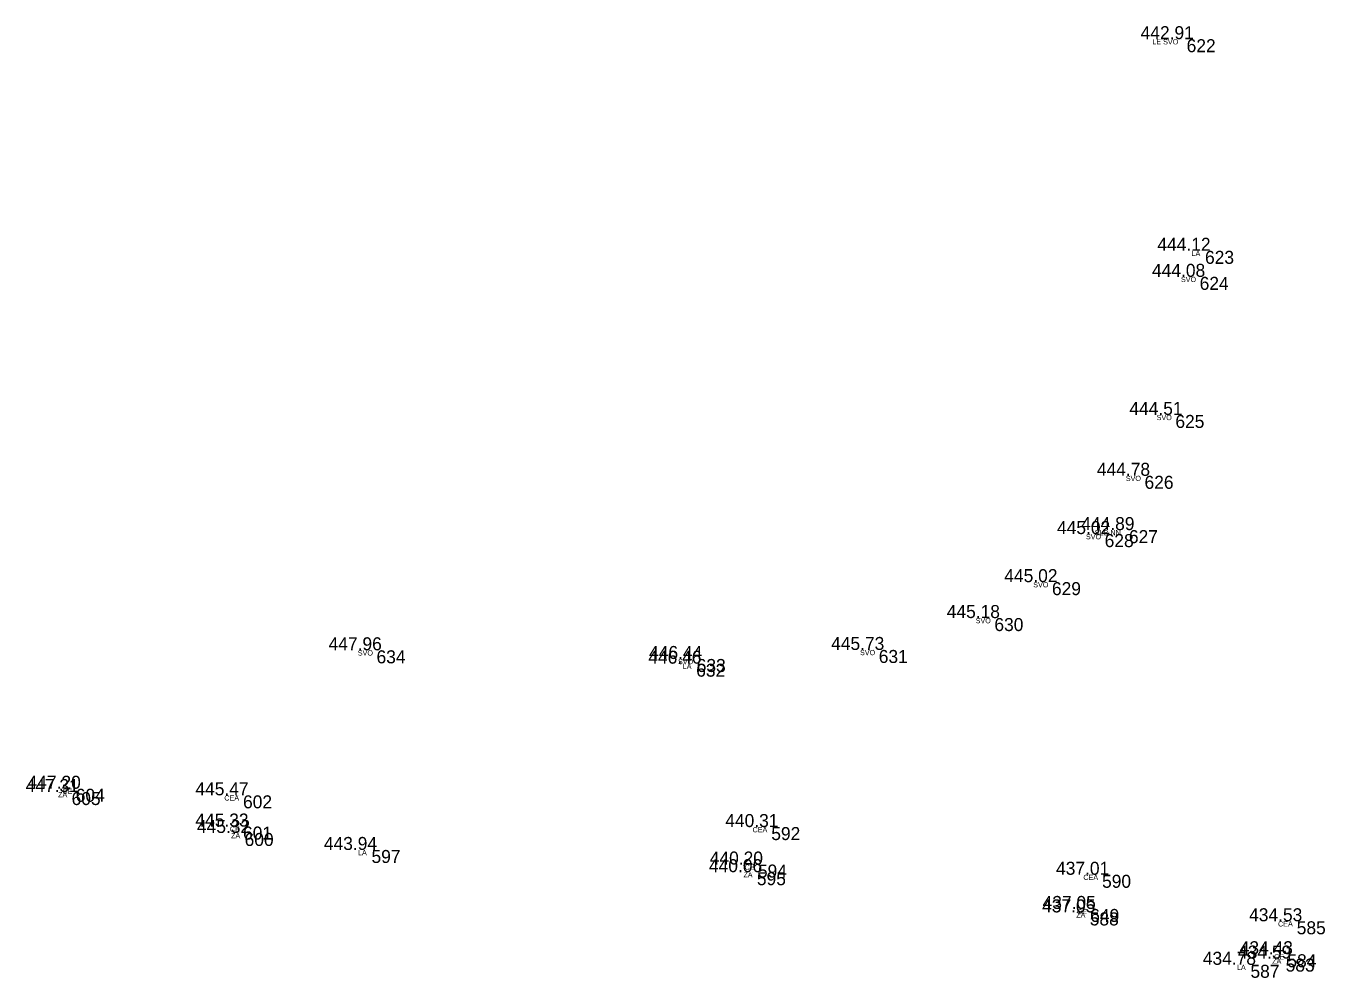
# Model space of a CAD drawing. Extents: x -639373 to -639057, y -1138651 to -1138359.
# Drawn here: x -639373.4 to -639298.5, y -1138578.8 to -1138523.9 of the extents above; entities that cross this region are included whole.
import ezdxf

# ---------------------------------------------------------------- set-up
doc = ezdxf.new("R2010")
doc.units = 0
for name, color, linetype in [('Vrstva 11', 7, 'Continuous'), ('Vrstva 12', 7, 'Continuous'), ('Vrstva 13', 7, 'Continuous'), ('Vrstva 57', 7, 'Continuous')]:
    doc.layers.add(name, color=color, linetype=linetype)

msp = doc.modelspace()

# ---------------------------------------------------------------- linework, layer by layer
at = {"layer": 'Vrstva 11'}
for p, q in [((-639306.73, -1138524.65), (-639306.73, -1138524.65)), ((-639305.67, -1138536.85), (-639305.67, -1138536.85)), ((-639305.98, -1138538.35), (-639305.98, -1138538.35)), ((-639307.38, -1138546.31), (-639307.38, -1138546.31)), ((-639309.16, -1138549.82), (-639309.16, -1138549.82)), ((-639310.06, -1138552.95), (-639310.06, -1138552.95)), ((-639311.46, -1138553.18), (-639311.46, -1138553.18)), ((-639314.5, -1138555.95), (-639314.5, -1138555.95)), ((-639317.82, -1138558.02), (-639317.82, -1138558.02)), ((-639353.46, -1138559.88), (-639353.46, -1138559.88)), ((-639334.99, -1138560.38), (-639334.99, -1138560.38)), ((-639324.49, -1138559.86), (-639324.49, -1138559.86)), ((-639335.02, -1138560.65), (-639335.02, -1138560.65)), ((-639370.81, -1138567.86), (-639370.81, -1138567.86)), ((-639371.05, -1138568.05), (-639371.05, -1138568.05)), ((-639361.16, -1138568.24), (-639361.16, -1138568.24)), ((-639361.16, -1138570.04), (-639361.16, -1138570.04)), ((-639330.69, -1138570.07), (-639330.69, -1138570.07)), ((-639361.07, -1138570.41), (-639361.07, -1138570.41)), ((-639353.75, -1138571.39), (-639353.75, -1138571.39)), ((-639331.46, -1138572.23), (-639331.46, -1138572.23)), ((-639331.52, -1138572.67), (-639331.52, -1138572.67)), ((-639311.61, -1138572.82), (-639311.61, -1138572.82)), ((-639312.32, -1138574.99), (-639312.32, -1138574.99)), ((-639312.29, -1138574.79), (-639312.29, -1138574.79)), ((-639300.38, -1138575.5), (-639300.38, -1138575.5)), ((-639301.02, -1138577.65), (-639301.02, -1138577.65)), ((-639300.92, -1138577.4), (-639300.92, -1138577.4)), ((-639303.05, -1138578.01), (-639303.05, -1138578.01))]:
    msp.add_line(p, q, dxfattribs=at)

# ---------------------------------------------------------------- texts
at = {"layer": 'Vrstva 12'}
for s, p in [('442.91 ', (-639309.105, -1138524.65)), ('444.12 ', (-639308.139, -1138536.85)), ('444.08 ', (-639308.449, -1138538.35)), ('444.51 ', (-639309.755, -1138546.31)), ('444.78 ', (-639311.629, -1138549.82)), ('444.89 ', (-639312.529, -1138552.95)), ('445.02 ', (-639313.929, -1138553.18)), ('445.02 ', (-639316.969, -1138555.95)), ('445.18 ', (-639320.289, -1138558.02)), ('447.96 ', (-639355.946, -1138559.88)), ('446.44 ', (-639337.459, -1138560.38)), ('445.73 ', (-639326.959, -1138559.86)), ('446.46 ', (-639337.506, -1138560.65)), ('447.20 ', (-639373.309, -1138567.86)), ('447.31 ', (-639373.425, -1138568.05)), ('445.47 ', (-639363.629, -1138568.24)), ('445.33 ', (-639363.629, -1138570.04)), ('440.31 ', (-639333.065, -1138570.07)), ('445.32 ', (-639363.539, -1138570.41)), ('443.94 ', (-639356.219, -1138571.39)), ('440.20 ', (-639333.959, -1138572.23)), ('440.06 ', (-639334.006, -1138572.67)), ('437.01 ', (-639313.985, -1138572.82)), ('437.05 ', (-639314.79, -1138574.99)), ('437.05 ', (-639314.76, -1138574.79)), ('434.53 ', (-639302.849, -1138575.5)), ('434.59 ', (-639303.489, -1138577.65)), ('434.43 ', (-639303.389, -1138577.4)), ('434.78 ', (-639305.519, -1138578.01))]:
    msp.add_text(s, height=0.75, dxfattribs=at).set_placement(p)
at = {"layer": 'Vrstva 13'}
for s, p in [(' 622', (-639306.73, -1138525.4)), (' 623', (-639305.67, -1138537.6)), (' 624', (-639305.98, -1138539.1)), (' 625', (-639307.38, -1138547.06)), (' 626', (-639309.16, -1138550.57)), (' 627', (-639310.06, -1138553.7)), (' 628', (-639311.46, -1138553.93)), (' 629', (-639314.5, -1138556.7)), (' 630', (-639317.82, -1138558.77)), (' 634', (-639353.46, -1138560.63)), (' 633', (-639334.99, -1138561.13)), (' 631', (-639324.49, -1138560.61)), (' 632', (-639335.02, -1138561.4)), (' 604', (-639370.81, -1138568.61)), (' 605', (-639371.05, -1138568.8)), (' 602', (-639361.16, -1138568.99)), (' 601', (-639361.16, -1138570.79)), (' 592', (-639330.69, -1138570.82)), (' 600', (-639361.07, -1138571.16)), (' 597', (-639353.75, -1138572.14)), (' 594', (-639331.46, -1138572.98)), (' 595', (-639331.52, -1138573.42)), (' 590', (-639311.61, -1138573.57)), (' 588', (-639312.32, -1138575.74)), (' 649', (-639312.29, -1138575.54)), (' 585', (-639300.38, -1138576.25)), (' 583', (-639301.02, -1138578.4)), (' 584', (-639300.92, -1138578.15)), (' 587', (-639303.05, -1138578.76))]:
    msp.add_text(s, height=0.75, dxfattribs=at).set_placement(p)
at = {"layer": 'Vrstva 57'}
for s, p in [('LE SVO', (-639308.431, -1138524.95)), ('LA', (-639306.17, -1138537.15)), ('SVO', (-639306.781, -1138538.65)), ('SVO', (-639308.181, -1138546.61)), ('SVO', (-639309.961, -1138550.12)), ('SLB NN', (-639311.749, -1138553.25)), ('SVO', (-639312.261, -1138553.48)), ('SVO', (-639315.301, -1138556.25)), ('SVO', (-639318.621, -1138558.32)), ('SVO', (-639354.261, -1138560.18)), ('SVO', (-639335.791, -1138560.68)), ('SVO', (-639325.291, -1138560.16)), ('LA', (-639335.52, -1138560.95)), ('CE', (-639371.297, -1138568.16)), ('ZA', (-639371.55, -1138568.35)), ('CEA', (-639361.96, -1138568.54)), ('CE', (-639361.647, -1138570.34)), ('CEA', (-639331.49, -1138570.37)), ('ZA', (-639361.57, -1138570.71)), ('LA', (-639354.25, -1138571.69)), ('CE', (-639331.948, -1138572.53)), ('ZA', (-639332.02, -1138572.97)), ('CEA', (-639312.41, -1138573.12)), ('ZA', (-639312.82, -1138575.29)), ('CE', (-639312.777, -1138575.09)), ('CEA', (-639301.18, -1138575.8)), ('ZA', (-639301.52, -1138577.95)), ('CE', (-639301.407, -1138577.7)), ('LA', (-639303.55, -1138578.31))]:
    msp.add_text(s, height=0.3, dxfattribs=at).set_placement(p)

doc.saveas('drawing.dxf')
